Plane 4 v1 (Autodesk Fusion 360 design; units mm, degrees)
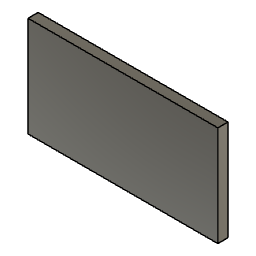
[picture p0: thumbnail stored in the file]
sketch "Sketch1" plane through (0, 0, 0) normal (0, 1, 0) x axis (1, 0, 0)
  line L1 (187.57, 0) -> (0, 0)
  line L2 (187.57, -99) -> (187.57, 0)
  line L3 (0, -99) -> (187.57, -99)
  line L4 (0, 0) -> (0, -99)
  point P1 (0, 0)
  point P2 (0, 0)
  point P3 (187.57, 0)
  point P5 (0, -99)
  horizontal L1
  vertical L2
  horizontal L3
  vertical L4
  coincident P1 P2
  dimension "d1" distance P2 P3 = 187.57
  dimension "d2" distance P2 P5 = 99
extrude "Extrude1" new body sketch "Sketch1" along normal blind 10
